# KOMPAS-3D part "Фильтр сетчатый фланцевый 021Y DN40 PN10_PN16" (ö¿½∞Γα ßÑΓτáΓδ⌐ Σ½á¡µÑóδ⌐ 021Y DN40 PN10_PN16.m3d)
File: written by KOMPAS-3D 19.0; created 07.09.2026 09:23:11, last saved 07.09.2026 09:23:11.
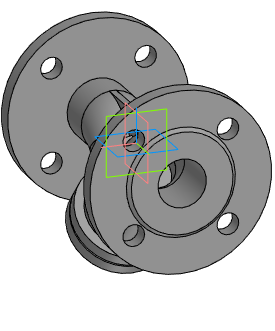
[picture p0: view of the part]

Document properties: Автор: Энергия; Полное имя файла: Z:\3.Личные\sachek\Dendor\_3D для проектировщиков\8.3 Фильтр сетчатый 021Y\021Y_STP\Фильтр сетчатый фланцевый 021Y DN40 PN10_PN16.m3d

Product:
- Part/product: Фильтр сетчатый фланцевый 021Y DN40 PN10_PN16

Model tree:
1. Операция без истории:1  (labels: Фильтр сетчатый фланцевый 021Y DN40 PN10_PN16)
